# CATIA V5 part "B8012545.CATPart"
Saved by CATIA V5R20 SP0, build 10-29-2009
Part number: B8012545
Revision: 6
Definition: design
Nomenclature: B8012545
Source: made
Description: NOT SPECIFIED
Bounding box of the stored display mesh (mm): x -22.5 to 22.5, y -22.5 to 22.5, z 0 to 45
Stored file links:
  C:\Users\Utente\Desktop\3D files B801\B8012545.CATPart
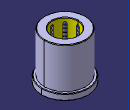
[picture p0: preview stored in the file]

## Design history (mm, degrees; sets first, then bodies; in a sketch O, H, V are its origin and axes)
Body1 "MANIFOLD_SOLID_BREP #38" (main body)
  Solid1: solid without history
Body2 "MANIFOLD_SOLID_BREP #76"
  Solid2: solid without history
Body3 "MANIFOLD_SOLID_BREP #114"
  Solid3: solid without history
Body4 "MANIFOLD_SOLID_BREP #152"
  Solid4: solid without history
Body5 "MANIFOLD_SOLID_BREP #190"
  Solid5: solid without history
Body6 "MANIFOLD_SOLID_BREP #228"
  Solid6: solid without history
Body7 "MANIFOLD_SOLID_BREP #266"
  Solid7: solid without history
Body8 "MANIFOLD_SOLID_BREP #304"
  Solid8: solid without history
Body9 "MANIFOLD_SOLID_BREP #342"
  Solid9: solid without history
Body10 "MANIFOLD_SOLID_BREP #2272"
  Solid10: solid without history
Body11 "MANIFOLD_SOLID_BREP #2310"
  Solid11: solid without history
Body12 "MANIFOLD_SOLID_BREP #2348"
  Solid12: solid without history
Body13 "MANIFOLD_SOLID_BREP #2386"
  Solid13: solid without history
Body14 "MANIFOLD_SOLID_BREP #2424"
  Solid14: solid without history
Body15 "MANIFOLD_SOLID_BREP #2462"
  Solid15: solid without history
Body16 "MANIFOLD_SOLID_BREP #2500"
  Solid16: solid without history
Body17 "MANIFOLD_SOLID_BREP #2538"
  Solid17: solid without history
Body18 "MANIFOLD_SOLID_BREP #2576"
  Solid18: solid without history
Body19 "MANIFOLD_SOLID_BREP #2614"
  Solid19: solid without history
Body20 "MANIFOLD_SOLID_BREP #2652"
  Solid20: solid without history
Body21 "MANIFOLD_SOLID_BREP #2690"
  Solid21: solid without history
Body22 "MANIFOLD_SOLID_BREP #2728"
  Solid22: solid without history
Body23 "MANIFOLD_SOLID_BREP #2766"
  Solid23: solid without history
Body24 "MANIFOLD_SOLID_BREP #2804"
  Solid24: solid without history
Body25 "MANIFOLD_SOLID_BREP #2842"
  Solid25: solid without history
Body26 "MANIFOLD_SOLID_BREP #2880"
  Solid26: solid without history
Body27 "MANIFOLD_SOLID_BREP #2918"
  Solid27: solid without history
Body28 "MANIFOLD_SOLID_BREP #2956"
  Solid28: solid without history
Body29 "MANIFOLD_SOLID_BREP #2994"
  Solid29: solid without history
Body30 "MANIFOLD_SOLID_BREP #3032"
  Solid30: solid without history
Body31 "MANIFOLD_SOLID_BREP #3070"
  Solid31: solid without history
Body32 "MANIFOLD_SOLID_BREP #3108"
  Solid32: solid without history
Body33 "MANIFOLD_SOLID_BREP #3146"
  Solid33: solid without history
Body34 "MANIFOLD_SOLID_BREP #3184"
  Solid34: solid without history
Body35 "MANIFOLD_SOLID_BREP #3222"
  Solid35: solid without history
Body36 "MANIFOLD_SOLID_BREP #3260"
  Solid36: solid without history
Body37 "MANIFOLD_SOLID_BREP #3298"
  Solid37: solid without history
Body38 "MANIFOLD_SOLID_BREP #3336"
  Solid38: solid without history
Body39 "MANIFOLD_SOLID_BREP #3374"
  Solid39: solid without history
Body40 "MANIFOLD_SOLID_BREP #3412"
  Solid40: solid without history
Body41 "MANIFOLD_SOLID_BREP #3450"
  Solid41: solid without history
Body42 "MANIFOLD_SOLID_BREP #3488"
  Solid42: solid without history
Body43 "MANIFOLD_SOLID_BREP #3526"
  Solid43: solid without history
Body44 "MANIFOLD_SOLID_BREP #3564"
  Solid44: solid without history
Body45 "MANIFOLD_SOLID_BREP #3602"
  Solid45: solid without history
Body46 "MANIFOLD_SOLID_BREP #3640"
  Solid46: solid without history
Body47 "MANIFOLD_SOLID_BREP #3678"
  Solid47: solid without history
Body48 "MANIFOLD_SOLID_BREP #3716"
  Solid48: solid without history
Body49 "MANIFOLD_SOLID_BREP #3754"
  Solid49: solid without history
Body50 "MANIFOLD_SOLID_BREP #3792"
  Solid50: solid without history
Body51 "MANIFOLD_SOLID_BREP #3830"
  Solid51: solid without history
Body52 "MANIFOLD_SOLID_BREP #3868"
  Solid52: solid without history
Body53 "MANIFOLD_SOLID_BREP #3906"
  Solid53: solid without history
Body54 "MANIFOLD_SOLID_BREP #3944"
  Solid54: solid without history
Body55 "MANIFOLD_SOLID_BREP #3982"
  Solid55: solid without history
Body56 "MANIFOLD_SOLID_BREP #4020"
  Solid56: solid without history
Body57 "MANIFOLD_SOLID_BREP #4058"
  Solid57: solid without history
Body58 "MANIFOLD_SOLID_BREP #4096"
  Solid58: solid without history
Body59 "MANIFOLD_SOLID_BREP #4134"
  Solid59: solid without history
Body60 "MANIFOLD_SOLID_BREP #4172"
  Solid60: solid without history
Body61 "MANIFOLD_SOLID_BREP #4210"
  Solid61: solid without history
Body62 "MANIFOLD_SOLID_BREP #4248"
  Solid62: solid without history
Body63 "MANIFOLD_SOLID_BREP #4286"
  Solid63: solid without history
Body64 "MANIFOLD_SOLID_BREP #4324"
  Solid64: solid without history
Body65 "MANIFOLD_SOLID_BREP #4362"
  Solid65: solid without history
Body66 "MANIFOLD_SOLID_BREP #4400"
  Solid66: solid without history
Body67 "MANIFOLD_SOLID_BREP #4438"
  Solid67: solid without history
Body68 "MANIFOLD_SOLID_BREP #4476"
  Solid68: solid without history
Body69 "MANIFOLD_SOLID_BREP #4514"
  Solid69: solid without history
Body70 "MANIFOLD_SOLID_BREP #4552"
  Solid70: solid without history
Body71 "MANIFOLD_SOLID_BREP #4590"
  Solid71: solid without history
Body72 "MANIFOLD_SOLID_BREP #4628"
  Solid72: solid without history
Body73 "MANIFOLD_SOLID_BREP #4666"
  Solid73: solid without history
Body74 "MANIFOLD_SOLID_BREP #4704"
  Solid74: solid without history
Body75 "MANIFOLD_SOLID_BREP #4742"
  Solid75: solid without history
Body76 "MANIFOLD_SOLID_BREP #4780"
  Solid76: solid without history
Body77 "MANIFOLD_SOLID_BREP #4818"
  Solid77: solid without history
Body78 "MANIFOLD_SOLID_BREP #4856"
  Solid78: solid without history
Body79 "MANIFOLD_SOLID_BREP #4894"
  Solid79: solid without history
Body80 "MANIFOLD_SOLID_BREP #4932"
  Solid80: solid without history
Body81 "MANIFOLD_SOLID_BREP #4970"
  Solid81: solid without history
Body82 "MANIFOLD_SOLID_BREP #5008"
  Solid82: solid without history
Body83 "MANIFOLD_SOLID_BREP #5046"
  Solid83: solid without history
Body84 "MANIFOLD_SOLID_BREP #5084"
  Solid84: solid without history
Body85 "MANIFOLD_SOLID_BREP #5122"
  Solid85: solid without history
Body86 "MANIFOLD_SOLID_BREP #5160"
  Solid86: solid without history
Body87 "MANIFOLD_SOLID_BREP #5198"
  Solid87: solid without history
Body88 "MANIFOLD_SOLID_BREP #5236"
  Solid88: solid without history
Body89 "MANIFOLD_SOLID_BREP #5274"
  Solid89: solid without history
Body90 "MANIFOLD_SOLID_BREP #5312"
  Solid90: solid without history
Body91 "MANIFOLD_SOLID_BREP #5350"
  Solid91: solid without history
Body92 "MANIFOLD_SOLID_BREP #5388"
  Solid92: solid without history
Body93 "MANIFOLD_SOLID_BREP #5426"
  Solid93: solid without history
Body94 "MANIFOLD_SOLID_BREP #5464"
  Solid94: solid without history
Body95 "MANIFOLD_SOLID_BREP #5502"
  Solid95: solid without history
Body96 "MANIFOLD_SOLID_BREP #5540"
  Solid96: solid without history
Body97 "MANIFOLD_SOLID_BREP #5578"
  Solid97: solid without history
